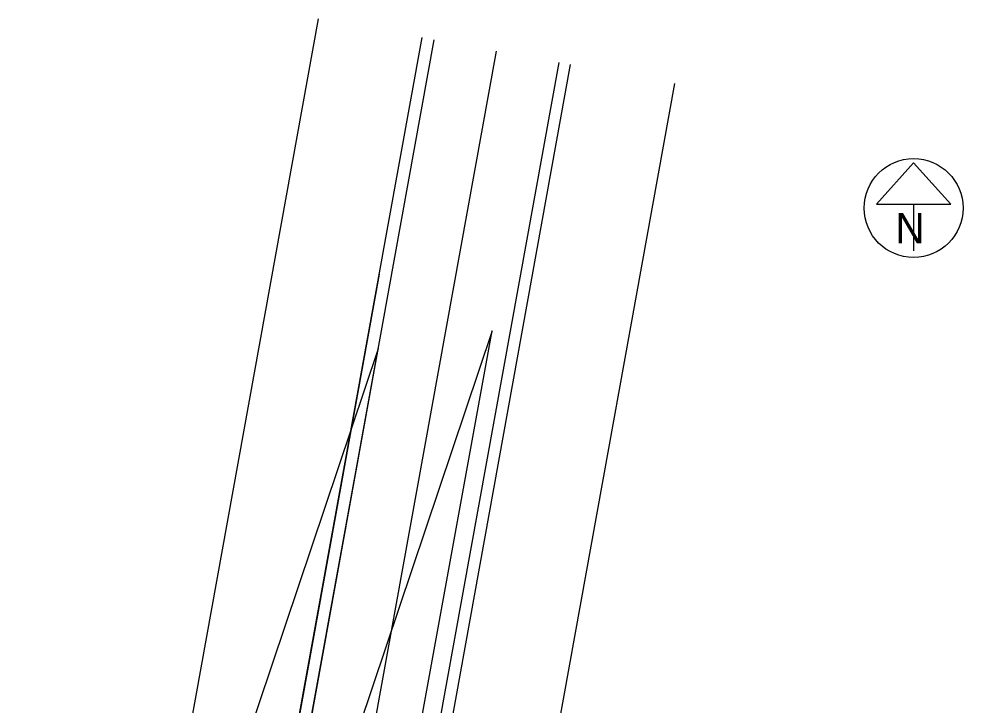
# Model space of a CAD drawing. Extents: x 1815539 to 1947826, y 273303 to 993194.
# Drawn here: x 1875891 to 1876047.5, y 317890.6 to 318004.4 of the extents above; entities that cross this region are included whole.
import ezdxf

# ---------------------------------------------------------------- set-up
doc = ezdxf.new("R2010")
doc.units = 0
for name, color, linetype in [('DT_P_Graded_Shoulder', 7, 'Continuous'), ('GE_P_Alignment', 7, 'Continuous'), ('PM_P_Edge_Line', 7, 'Continuous'), ('PV_P_EOP', 7, 'Continuous'), ('RW_X_Fee_RW', 7, 'Continuous'), ('SC_Scratch1', 7, 'Continuous'), ('SH_Masking', 7, 'Continuous'), ('SH_Text', 7, 'Continuous')]:
    doc.layers.add(name, color=color, linetype=linetype)

msp = doc.modelspace()

# ---------------------------------------------------------------- linework, layer by layer
at = {"layer": 'DT_P_Graded_Shoulder'}
msp.add_lwpolyline([(1875950.77, 317962.07), (1875919.46, 317789.12), (1875915.6, 317767.77)], dxfattribs=at)
at = {"layer": 'GE_P_Alignment'}
msp.add_line((1875970.16, 317999.04), (1875919.23, 317717.68), dxfattribs=at)
at = {"layer": 'PM_P_Edge_Line'}
for p, q in [((1875959.83, 318000.91), (1875917.61, 317767.67)), ((1875980.5, 317997.17), (1875942.2, 317785.6))]:
    msp.add_line(p, q, dxfattribs=at)
at = {"layer": 'PV_P_EOP'}
for p, q in [((1875915.64, 317768.03), (1875957.86, 318001.27)), ((1875944.17, 317785.24), (1875982.47, 317996.81))]:
    msp.add_line(p, q, dxfattribs=at)
at = {"layer": 'RW_X_Fee_RW'}
for p, q in [((1875940.64, 318004.38), (1875894.42, 317749.03)), ((1875999.69, 317993.69), (1875954.82, 317745.83))]:
    msp.add_line(p, q, dxfattribs=at)
at = {"layer": 'SC_Scratch1'}
for p, q in [((1875936.5, 317770.66), (1875969.45, 317952.7)), ((1875917.61, 317767.67), (1875950.57, 317949.71))]:
    msp.add_line(p, q, dxfattribs=at)
for points in [[(1875969.45, 317952.7), (1875909.93, 317775.47), (1875936.5, 317770.66)], [(1875950.57, 317949.71), (1875891.04, 317772.48), (1875917.61, 317767.67)]]:
    msp.add_lwpolyline(points, dxfattribs=at)
at = {"layer": 'SH_Masking'}
msp.add_circle((1876039.32, 317973.03), 8.2, dxfattribs=at)
at = {"layer": 'SH_Text'}
for p, q in [((1876039.32, 317980.5), (1876033.17, 317973.68)), ((1876045.47, 317973.68), (1876039.32, 317980.5)), ((1876033.17, 317973.68), (1876045.47, 317973.68)), ((1876039.32, 317973.68), (1876039.32, 317965.94))]:
    msp.add_line(p, q, dxfattribs=at)
msp.add_circle((1876039.32, 317973.03), 8.2, dxfattribs=at)

# ---------------------------------------------------------------- texts
msp.add_text('N', height=5, rotation=359.9988, dxfattribs=at).set_placement((1876036.3, 317967.2))

doc.saveas('drawing.dxf')
